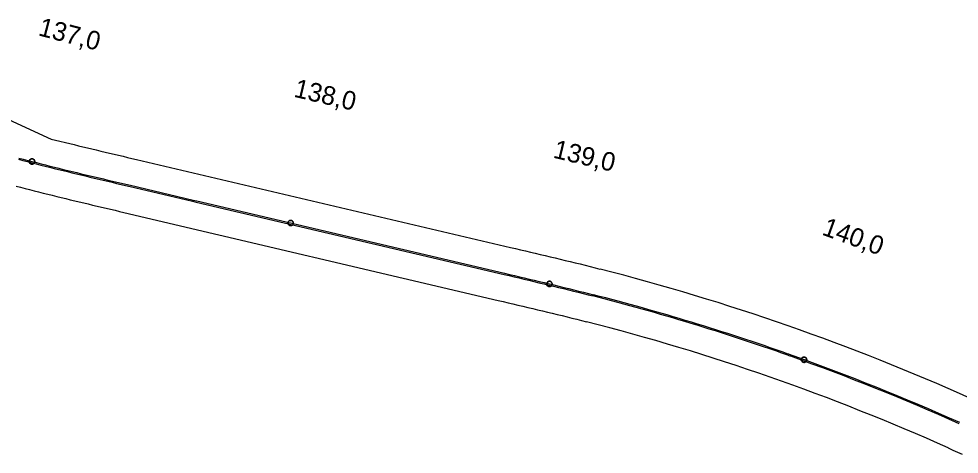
# Model space of a CAD drawing. Extents: x -670810 to -649614, y -1131928 to -1115069.
# Drawn here: x -661499 to -657961, y -1129345 to -1127707 of the extents above; entities that cross this region are included whole.
import ezdxf

# ---------------------------------------------------------------- set-up
doc = ezdxf.new("R2010")
doc.units = 0
for name, color, linetype in [('hranice_VRT_ZUR_Vysocina', 7, 'Continuous'), ('Situace - Osa koleje 2D', 7, 'Continuous'), ('Situace - Osa koleje tunel 2D', 7, 'Continuous'), ('Staničení - hlavní staničení + kolečka 1k', 7, 'Continuous')]:
    doc.layers.add(name, color=color, linetype=linetype)

# ---------------------------------------------------------------- blocks, each defined once
blk = doc.blocks.new('Sit10Kruh_114')
at = {"layer": 'Staničení - hlavní staničení + kolečka 1k'}
blk.add_lwpolyline([(10, 0), (10, 0.6), (9.9, 1.3), (9.8, 1.9), (9.7, 2.5), (9.5, 3.1), (9.3, 3.7), (9, 4.3), (8.8, 4.8), (8.4, 5.4), (8.1, 5.9), (7.7, 6.4), (7.3, 6.8), (6.8, 7.3), (6.4, 7.7), (5.9, 8.1), (5.4, 8.4), (4.8, 8.8), (4.3, 9), (3.7, 9.3), (3.1, 9.5), (2.5, 9.7), (1.9, 9.8), (1.3, 9.9), (0.6, 10), (0, 10), (-0.6, 10), (-1.3, 9.9), (-1.9, 9.8), (-2.5, 9.7), (-3.1, 9.5), (-3.7, 9.3), (-4.3, 9), (-4.8, 8.8), (-5.4, 8.4), (-5.9, 8.1), (-6.4, 7.7), (-6.8, 7.3), (-7.3, 6.8), (-7.7, 6.4), (-8.1, 5.9), (-8.4, 5.4), (-8.8, 4.8), (-9, 4.3), (-9.3, 3.7), (-9.5, 3.1), (-9.7, 2.5), (-9.8, 1.9), (-9.9, 1.3), (-10, 0.6), (-10, 0), (-10, -0.6), (-9.9, -1.3), (-9.8, -1.9), (-9.7, -2.5), (-9.5, -3.1), (-9.3, -3.7), (-9, -4.3), (-8.8, -4.8), (-8.4, -5.4), (-8.1, -5.9), (-7.7, -6.4), (-7.3, -6.8), (-6.8, -7.3), (-6.4, -7.7), (-5.9, -8.1), (-5.4, -8.4), (-4.8, -8.8), (-4.3, -9), (-3.7, -9.3), (-3.1, -9.5), (-2.5, -9.7), (-1.9, -9.8), (-1.3, -9.9), (-0.6, -10), (0, -10), (0.6, -10), (1.3, -9.9), (1.9, -9.8), (2.5, -9.7), (3.1, -9.5), (3.7, -9.3), (4.3, -9), (4.8, -8.8), (5.4, -8.4), (5.9, -8.1), (6.4, -7.7), (6.8, -7.3), (7.3, -6.8), (7.7, -6.4), (8.1, -5.9), (8.4, -5.4), (8.8, -4.8), (9, -4.3), (9.3, -3.7), (9.5, -3.1), (9.7, -2.5), (9.8, -1.9), (9.9, -1.3)], close=True, dxfattribs=at)
blk.add_circle((0, 0), 10, dxfattribs=at)
blk = doc.blocks.new('Sit10Kruh_115')
at = {"layer": 'Staničení - hlavní staničení + kolečka 1k'}
blk.add_lwpolyline([(10, 0), (9.98026, 0.6279), (9.92114, 1.25334), (9.82288, 1.87382), (9.68584, 2.4869), (9.51056, 3.09016), (9.29776, 3.68124), (9.04828, 4.2578), (8.76306, 4.81754), (8.44328, 5.35826), (8.09016, 5.87786), (7.70514, 6.37424), (7.28968, 6.84548), (6.84548, 7.28968), (6.37424, 7.70514), (5.87786, 8.09016), (5.35826, 8.44328), (4.81754, 8.76306), (4.2578, 9.04828), (3.68124, 9.29776), (3.09016, 9.51056), (2.4869, 9.68584), (1.87382, 9.82288), (1.25334, 9.92114), (0.6279, 9.98026), (0, 10), (-0.6279, 9.98026), (-1.25334, 9.92114), (-1.87382, 9.82288), (-2.4869, 9.68584), (-3.09016, 9.51056), (-3.68124, 9.29776), (-4.2578, 9.04828), (-4.81754, 8.76306), (-5.35826, 8.44328), (-5.87786, 8.09016), (-6.37424, 7.70514), (-6.84548, 7.28968), (-7.28968, 6.84548), (-7.70514, 6.37424), (-8.09016, 5.87786), (-8.44328, 5.35826), (-8.76306, 4.81754), (-9.04828, 4.2578), (-9.29776, 3.68124), (-9.51056, 3.09016), (-9.68584, 2.4869), (-9.82288, 1.87382), (-9.92114, 1.25334), (-9.98026, 0.6279), (-10, 0), (-9.98026, -0.6279), (-9.92114, -1.25334), (-9.82288, -1.87382), (-9.68584, -2.4869), (-9.51056, -3.09016), (-9.29776, -3.68124), (-9.04828, -4.2578), (-8.76306, -4.81754), (-8.44328, -5.35826), (-8.09016, -5.87786), (-7.70514, -6.37424), (-7.28968, -6.84548), (-6.84548, -7.28968), (-6.37424, -7.70514), (-5.87786, -8.09016), (-5.35826, -8.44328), (-4.81754, -8.76306), (-4.2578, -9.04828), (-3.68124, -9.29776), (-3.09016, -9.51056), (-2.4869, -9.68584), (-1.87382, -9.82288), (-1.25334, -9.92114), (-0.6279, -9.98026), (0, -10), (0.6279, -9.98026), (1.25334, -9.92114), (1.87382, -9.82288), (2.4869, -9.68584), (3.09016, -9.51056), (3.68124, -9.29776), (4.2578, -9.04828), (4.81754, -8.76306), (5.35826, -8.44328), (5.87786, -8.09016), (6.37424, -7.70514), (6.84548, -7.28968), (7.28968, -6.84548), (7.70514, -6.37424), (8.09016, -5.87786), (8.44328, -5.35826), (8.76306, -4.81754), (9.04828, -4.2578), (9.29776, -3.68124), (9.51056, -3.09016), (9.68584, -2.4869), (9.82288, -1.87382), (9.92114, -1.25334)], close=True, dxfattribs=at)
blk.add_circle((0, 0), 10, dxfattribs=at)
blk = doc.blocks.new('Sit10Kruh_116')
at = {"layer": 'Staničení - hlavní staničení + kolečka 1k'}
blk.add_lwpolyline([(10, 0), (9.98026, 0.6279), (9.92114, 1.25334), (9.82288, 1.87382), (9.68584, 2.4869), (9.51056, 3.09016), (9.29776, 3.68124), (9.04828, 4.2578), (8.76306, 4.81754), (8.44328, 5.35826), (8.09016, 5.87786), (7.70514, 6.37424), (7.28968, 6.84548), (6.84548, 7.28968), (6.37424, 7.70514), (5.87786, 8.09016), (5.35826, 8.44328), (4.81754, 8.76306), (4.2578, 9.04828), (3.68124, 9.29776), (3.09016, 9.51056), (2.4869, 9.68584), (1.87382, 9.82288), (1.25334, 9.92114), (0.6279, 9.98026), (0, 10), (-0.6279, 9.98026), (-1.25334, 9.92114), (-1.87382, 9.82288), (-2.4869, 9.68584), (-3.09016, 9.51056), (-3.68124, 9.29776), (-4.2578, 9.04828), (-4.81754, 8.76306), (-5.35826, 8.44328), (-5.87786, 8.09016), (-6.37424, 7.70514), (-6.84548, 7.28968), (-7.28968, 6.84548), (-7.70514, 6.37424), (-8.09016, 5.87786), (-8.44328, 5.35826), (-8.76306, 4.81754), (-9.04828, 4.2578), (-9.29776, 3.68124), (-9.51056, 3.09016), (-9.68584, 2.4869), (-9.82288, 1.87382), (-9.92114, 1.25334), (-9.98026, 0.6279), (-10, 0), (-9.98026, -0.6279), (-9.92114, -1.25334), (-9.82288, -1.87382), (-9.68584, -2.4869), (-9.51056, -3.09016), (-9.29776, -3.68124), (-9.04828, -4.2578), (-8.76306, -4.81754), (-8.44328, -5.35826), (-8.09016, -5.87786), (-7.70514, -6.37424), (-7.28968, -6.84548), (-6.84548, -7.28968), (-6.37424, -7.70514), (-5.87786, -8.09016), (-5.35826, -8.44328), (-4.81754, -8.76306), (-4.2578, -9.04828), (-3.68124, -9.29776), (-3.09016, -9.51056), (-2.4869, -9.68584), (-1.87382, -9.82288), (-1.25334, -9.92114), (-0.6279, -9.98026), (0, -10), (0.6279, -9.98026), (1.25334, -9.92114), (1.87382, -9.82288), (2.4869, -9.68584), (3.09016, -9.51056), (3.68124, -9.29776), (4.2578, -9.04828), (4.81754, -8.76306), (5.35826, -8.44328), (5.87786, -8.09016), (6.37424, -7.70514), (6.84548, -7.28968), (7.28968, -6.84548), (7.70514, -6.37424), (8.09016, -5.87786), (8.44328, -5.35826), (8.76306, -4.81754), (9.04828, -4.2578), (9.29776, -3.68124), (9.51056, -3.09016), (9.68584, -2.4869), (9.82288, -1.87382), (9.92114, -1.25334)], close=True, dxfattribs=at)
blk.add_circle((0, 0), 10, dxfattribs=at)
blk = doc.blocks.new('Sit10Kruh_117')
at = {"layer": 'Staničení - hlavní staničení + kolečka 1k'}
blk.add_lwpolyline([(10, 0), (9.98026, 0.6279), (9.92114, 1.25334), (9.82288, 1.87382), (9.68584, 2.4869), (9.51056, 3.09016), (9.29776, 3.68124), (9.04828, 4.2578), (8.76306, 4.81754), (8.44328, 5.35826), (8.09016, 5.87786), (7.70514, 6.37424), (7.28968, 6.84548), (6.84548, 7.28968), (6.37424, 7.70514), (5.87786, 8.09016), (5.35826, 8.44328), (4.81754, 8.76306), (4.2578, 9.04828), (3.68124, 9.29776), (3.09016, 9.51056), (2.4869, 9.68584), (1.87382, 9.82288), (1.25334, 9.92114), (0.6279, 9.98026), (0, 10), (-0.6279, 9.98026), (-1.25334, 9.92114), (-1.87382, 9.82288), (-2.4869, 9.68584), (-3.09016, 9.51056), (-3.68124, 9.29776), (-4.2578, 9.04828), (-4.81754, 8.76306), (-5.35826, 8.44328), (-5.87786, 8.09016), (-6.37424, 7.70514), (-6.84548, 7.28968), (-7.28968, 6.84548), (-7.70514, 6.37424), (-8.09016, 5.87786), (-8.44328, 5.35826), (-8.76306, 4.81754), (-9.04828, 4.2578), (-9.29776, 3.68124), (-9.51056, 3.09016), (-9.68584, 2.4869), (-9.82288, 1.87382), (-9.92114, 1.25334), (-9.98026, 0.6279), (-10, 0), (-9.98026, -0.6279), (-9.92114, -1.25334), (-9.82288, -1.87382), (-9.68584, -2.4869), (-9.51056, -3.09016), (-9.29776, -3.68124), (-9.04828, -4.2578), (-8.76306, -4.81754), (-8.44328, -5.35826), (-8.09016, -5.87786), (-7.70514, -6.37424), (-7.28968, -6.84548), (-6.84548, -7.28968), (-6.37424, -7.70514), (-5.87786, -8.09016), (-5.35826, -8.44328), (-4.81754, -8.76306), (-4.2578, -9.04828), (-3.68124, -9.29776), (-3.09016, -9.51056), (-2.4869, -9.68584), (-1.87382, -9.82288), (-1.25334, -9.92114), (-0.6279, -9.98026), (0, -10), (0.6279, -9.98026), (1.25334, -9.92114), (1.87382, -9.82288), (2.4869, -9.68584), (3.09016, -9.51056), (3.68124, -9.29776), (4.2578, -9.04828), (4.81754, -8.76306), (5.35826, -8.44328), (5.87786, -8.09016), (6.37424, -7.70514), (6.84548, -7.28968), (7.28968, -6.84548), (7.70514, -6.37424), (8.09016, -5.87786), (8.44328, -5.35826), (8.76306, -4.81754), (9.04828, -4.2578), (9.29776, -3.68124), (9.51056, -3.09016), (9.68584, -2.4869), (9.82288, -1.87382), (9.92114, -1.25334)], close=True, dxfattribs=at)
blk.add_circle((0, 0), 10, dxfattribs=at)

msp = doc.modelspace()

# ---------------------------------------------------------------- linework, layer by layer
at = {"layer": 'hranice_VRT_ZUR_Vysocina'}
for points in [[(-662489.9, -1127774.2), (-661897.9, -1127961.1), (-661554.5, -1128077.7), (-661377.3, -1128159.3)], [(-661377.3, -1128159.3), (-661291, -1128180.4), (-661274.3, -1128184.4), (-661257.7, -1128188.5), (-661241, -1128192.5), (-661224.3, -1128196.5), (-661207.5, -1128200.5), (-661190.8, -1128204.4), (-661174, -1128208.4), (-661157.2, -1128212.4), (-661140.4, -1128216.3), (-661123.6, -1128220.3), (-661106.8, -1128224.2), (-661090, -1128228.2), (-661073.2, -1128232.1), (-661056.4, -1128236.1), (-659648.9, -1128567.1), (-659630.3, -1128571.5), (-659611.6, -1128575.9), (-659593, -1128580.3), (-659574.4, -1128584.7), (-659555.8, -1128589.1), (-659537.1, -1128593.5), (-659518.4, -1128597.9), (-659499.8, -1128602.3), (-659481.1, -1128606.8), (-659462.4, -1128611.3), (-659443.6, -1128615.8), (-659424.9, -1128620.3), (-659406.2, -1128624.9), (-659387.4, -1128629.5), (-659368.7, -1128634.2), (-659349.9, -1128638.9), (-659331.2, -1128643.6), (-659312.6, -1128648.4), (-659312.5, -1128648.4)], [(-661508.9, -1128336.3), (-661492, -1128340.8), (-661475, -1128345.2), (-661458.1, -1128349.6), (-661441.1, -1128354), (-661424.2, -1128358.3), (-661407.2, -1128362.6), (-661390.2, -1128366.8), (-661373.3, -1128371), (-661356.3, -1128375.2), (-661339.4, -1128379.3), (-661322.5, -1128383.4), (-661305.5, -1128387.5), (-661288.6, -1128391.6), (-661271.7, -1128395.6), (-661254.8, -1128399.6), (-661237.9, -1128403.6), (-661221.1, -1128407.6), (-661204.2, -1128411.6), (-661187.4, -1128415.6), (-661170.5, -1128419.5), (-661153.7, -1128423.5), (-661136.8, -1128427.5), (-661120, -1128431.4), (-661103.2, -1128435.4), (-659695.7, -1128766.4), (-659677.1, -1128770.8), (-659658.5, -1128775.2), (-659639.9, -1128779.5), (-659621.3, -1128783.9), (-659602.8, -1128788.3), (-659584.2, -1128792.7), (-659565.7, -1128797.1), (-659547.2, -1128801.5), (-659528.7, -1128805.9), (-659510.2, -1128810.3), (-659491.8, -1128814.7), (-659473.3, -1128819.2), (-659454.9, -1128823.7), (-659436.6, -1128828.2), (-659418.2, -1128832.8), (-659399.9, -1128837.4), (-659381.6, -1128842), (-659363.1, -1128846.7), (-659363.3, -1128846.7)], [(-658002.1, -1129321.9), (-658002.2, -1129321.9), (-657984.9, -1129329.7), (-657967.6, -1129337.4), (-657950.4, -1129345.3)]]:
    msp.add_lwpolyline(points, dxfattribs=at)
for centre, radius, start, end in [((-661474.3, -1137080.3), 8704.6, 65.88874, 75.6195), ((-661474.4, -1137080.3), 8500, 65.88908, 75.61916)]:
    msp.add_arc(centre, radius, start, end, dxfattribs=at)
at = {"layer": 'Situace - Osa koleje 2D'}
for p, q in [((-661080.3, -1128338), (-660844.9, -1128393.4)), ((-661079.3, -1128333.4), (-660842.4, -1128389.2)), ((-660829.7, -1128392.2), (-659671.8, -1128664.5)), ((-660832.2, -1128396.4), (-659672.8, -1128669.1))]:
    msp.add_line(p, q, dxfattribs=at)
for points in [[(-661500, -1128235.2), (-661483.3, -1128239.7), (-661466.6, -1128244.1), (-661449.9, -1128248.5), (-661433.1, -1128252.8), (-661416.4, -1128257.1), (-661399.6, -1128261.3), (-661382.9, -1128265.6), (-661366.1, -1128269.7), (-661349.3, -1128273.9), (-661332.5, -1128278), (-661315.7, -1128282.1), (-661298.9, -1128286.2), (-661282.1, -1128290.3), (-661265.3, -1128294.3), (-661248.5, -1128298.3), (-661231.7, -1128302.3), (-661214.9, -1128306.3), (-661198.1, -1128310.3), (-661181.2, -1128314.3), (-661164.4, -1128318.2), (-661147.6, -1128322.2), (-661130.8, -1128326.2), (-661113.9, -1128330.1), (-661097.1, -1128334.1), (-661080.3, -1128338)], [(-661498.9, -1128230.7), (-661482.2, -1128235.1), (-661465.5, -1128239.5), (-661448.7, -1128243.9), (-661432, -1128248.2), (-661415.3, -1128252.5), (-661398.5, -1128256.8), (-661381.8, -1128261), (-661365, -1128265.2), (-661348.2, -1128269.3), (-661331.4, -1128273.5), (-661314.7, -1128277.6), (-661297.9, -1128281.6), (-661281.1, -1128285.7), (-661264.3, -1128289.7), (-661247.5, -1128293.7), (-661230.6, -1128297.7), (-661213.8, -1128301.7), (-661197, -1128305.7), (-661180.2, -1128309.7), (-661163.4, -1128313.7), (-661146.6, -1128317.6), (-661129.7, -1128321.6), (-661112.9, -1128325.5), (-661096.1, -1128329.5), (-661079.3, -1128333.4)], [(-659672.8, -1128669.1), (-659654.2, -1128673.4), (-659635.6, -1128677.8), (-659617, -1128682.2), (-659598.4, -1128686.6), (-659579.8, -1128691), (-659561.2, -1128695.4), (-659542.6, -1128699.8), (-659524, -1128704.2), (-659505.4, -1128708.6), (-659486.8, -1128713.1), (-659468.2, -1128717.5), (-659449.7, -1128722.1), (-659431.1, -1128726.6), (-659412.5, -1128731.2), (-659394, -1128735.8), (-659375.5, -1128740.4), (-659356.9, -1128745.1), (-659338.4, -1128749.8)], [(-659671.8, -1128664.5), (-659653.2, -1128668.9), (-659634.5, -1128673.2), (-659615.9, -1128677.6), (-659597.3, -1128682), (-659578.7, -1128686.4), (-659560.1, -1128690.8), (-659541.5, -1128695.2), (-659522.9, -1128699.6), (-659504.3, -1128704), (-659485.7, -1128708.5), (-659467.2, -1128713), (-659448.6, -1128717.5), (-659430, -1128722), (-659411.4, -1128726.6), (-659392.9, -1128731.2), (-659374.4, -1128735.8), (-659355.8, -1128740.5), (-659337.3, -1128745.3)]]:
    msp.add_lwpolyline(points, dxfattribs=at)
for radius, start, end in [(8604.7, 70.51956, 75.61944), (8600, 70.51958, 75.61913), (8600, 65.8891, 70.43631), (8604.7, 65.88879, 70.43633)]:
    msp.add_arc((-661474.4, -1137080.4), radius, start, end, dxfattribs=at)
at = {"layer": 'Situace - Osa koleje tunel 2D'}
for p, q in [((-660844.9, -1128393.4), (-660832.2, -1128396.4)), ((-660842.4, -1128389.2), (-660829.7, -1128392.2))]:
    msp.add_line(p, q, dxfattribs=at)
for radius, start, end in [(8600, 70.43631, 70.51959), (8604.7, 70.43633, 70.51956)]:
    msp.add_arc((-661474.4, -1137080.4), radius, start, end, dxfattribs=at)

# ---------------------------------------------------------------- block references
at = {"layer": 'Staničení - hlavní staničení + kolečka 1k'}
for name, p, rotation in [('Sit10Kruh_114', (-661449.1, -1128243.8), -14.587100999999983), ('Sit10Kruh_115', (-660476.2, -1128475.3), -13.234954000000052), ('Sit10Kruh_116', (-659502.8, -1128704.4), -13.45486199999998), ('Sit10Kruh_117', (-658545, -1128989.7), -19.903762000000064)]:
    msp.add_blockref(name, p, dxfattribs=dict(at, rotation=rotation))

# ---------------------------------------------------------------- texts
for s, rotation, p in [('137,0', 345.4129, (-661429, -1127768.5)), ('138,0', 346.765, (-660467.4, -1127999.7)), ('139,0', 346.5452, (-659492.1, -1128228.8)), ('140,0', 340.0963, (-658480.9, -1128518.3))]:
    msp.add_text(s, height=70, rotation=rotation, dxfattribs=at).set_placement(p)

doc.saveas('drawing.dxf')
